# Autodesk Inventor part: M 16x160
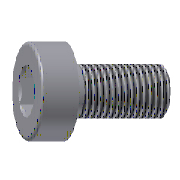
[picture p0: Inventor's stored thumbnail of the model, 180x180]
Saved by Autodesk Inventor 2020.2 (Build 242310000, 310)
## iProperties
Manager: www.cadconsulting.pl
Company: Fabian Stasiak CAD Consulting
Created: 2014-02
Part Number: M 16x160
Material: Stal, miękka
Description: Socket Head Cap Screw DIN 912 - 12.9
Document SubType Name: Modeling
Designer: F.Stasiak
Standard Revision: 1
Manufacturer: DME
Language: pl-PL
Size Designation: 16x160
Categories: <MemberInstance><Categories><Category DisplayName="Forma wtryskowa" InternalName="349578f2-f4d4-4954-8c09-8e99297a61c0" Mnemonic="MOLD"><Category DisplayName="C
Mass: 0.133121 g
Surface Area: 2.01441 cm^2
Volume: 0.133121 cm^3
Density: 7.85 g/cm^3
Appearance: Częściowo polerowana
Catalog Web Link: www.expertbooks.pl
IsCustomPart: 0
Author: F.Stasiak
Subject: Zbiór ćwiczeń. Autodesk Inventor 2020. Kurs Professional
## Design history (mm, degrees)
sketch "Sketch1"
  geometry: L1 (0, -195.2)-(0, 51.2) reference; L2 (8.083, 16)-(12, 16); L3 (12, 16)-(12, 0); L4 (12, 0)-(8, 0); L5 (8, 0)-(8, -160); L6 (8, -160)-(0, -160); L7 (0, 3.794)-(0, -160); L8 (0, 3.794)-(7, 8); L9 (7, 8)-(7, 14.917); L10 (7, 14.917)-(8.083, 16); 1 further point
  constraints: 18 end point, 4 vertical, 3 horizontal, 2 point on line
  dimensions: "d0" = 24 diameter of L3 L1 (= dk); "d1" = 16 distance between parallel lines of L4 L2 (= k); "d2" = 16 diameter of L5 L1 (= d); "d3" = 160 distance between parallel lines of L6 L4 (= L); "d4" = 59 deg angle of L1 L8; "d5" = 45 deg angle of L1 L10; "d6" = 14 diameter of L9 L1 (= sw); "d7" = 16.16581 diameter of L2.start L1 (= 1.1547 x sw); "d8" = 8 distance from line of L8.end L2 (= t)
revolve "Revolution1" sketch "Sketch1" stored, may be unused: angle "d44" = 90 deg
sketch "Sketch2"
  geometry: L1 (0, 8.083)-(7, 4.041); L2 (7, 4.041)-(7, -4.041); L3 (7, -4.041)-(0, -8.083); L4 (0, -8.083)-(-7, -4.041); L5 (-7, -4.041)-(-7, 4.041); L6 (-7, 4.041)-(0, 8.083); 3 further points
  constraints: 12 end point, 2 vertical alignment, 1 coincident, 14 other
extrude "Extrusion1" cut sketch "Sketch2" taper "d9" = 0 deg; stored distance "d45" = 10
thread "Thread1" dims "d10" = 44 (= b), "d11" = 0
chamfer "Chamfer1" distance "d12" = 1 (= 0.5 x P); stored, may be unused: second distance "d50" = 2, angle "d51" = 45 deg
fillet "Fillet1" dims "d13" = 1 (= 0.5 x P)
body "Solid1"
other parameters: "d" = 16 [user parameter; used in 1 equation term], "L" = 160 [user parameter; used in 1 equation term], "dk" = 24 [user parameter; used in 1 equation term], "b" = 44 [user parameter; used in 1 equation term], "k" = 16 [user parameter; used in 1 equation term], "sw" = 14 [user parameter; used in 2 equation terms], "t" = 8 [user parameter; used in 1 equation term], "P" = 2 [user parameter; used in 2 equation terms], "d14" = 0, "d15" = 0, "d55" = 0
